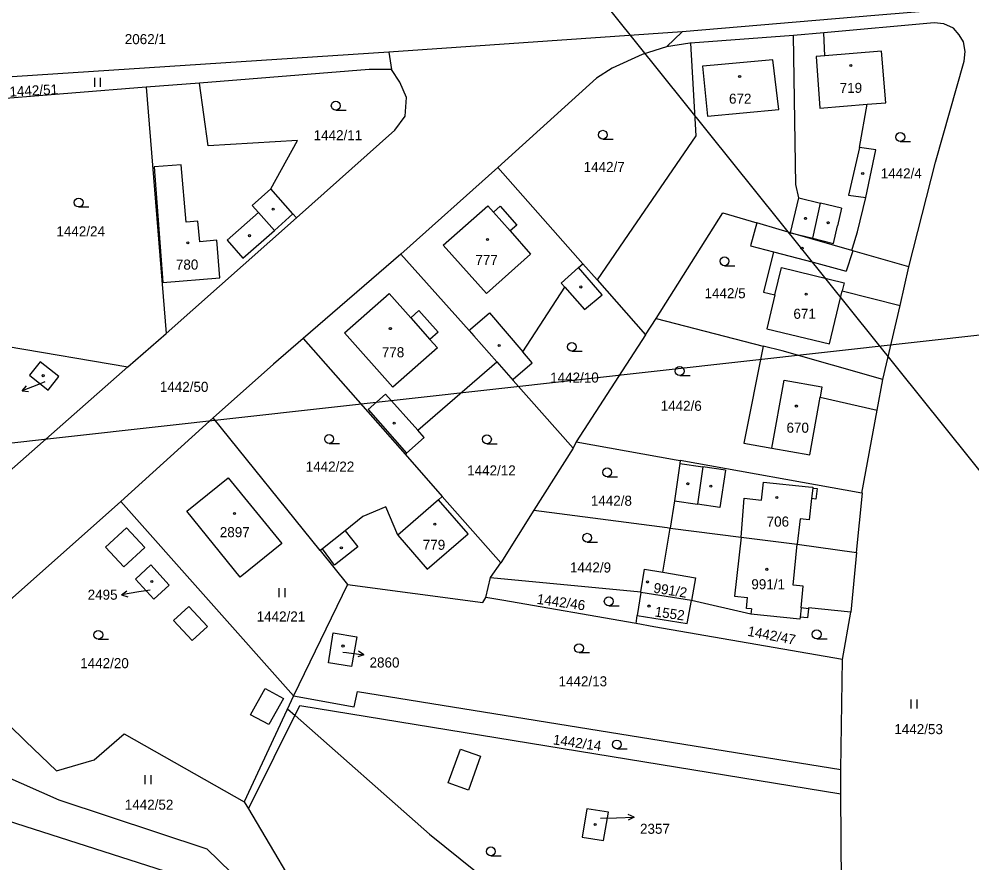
# Model space of a CAD drawing. Extents: x -794765 to -785424, y -1118958 to -1108731.
# Drawn here: x -792786.8 to -792625.5, y -1110305.2 to -1110162.4 of the extents above; entities that cross this region are included whole.
import ezdxf

# ---------------------------------------------------------------- set-up
doc = ezdxf.new("R2010")
doc.units = 0
for name, color, linetype in [('Level 66', 7, 'Continuous'), ('Level 71', 7, 'Continuous'), ('Level 75', 7, 'Continuous'), ('Level 76', 7, 'Continuous'), ('Level 77', 7, 'Continuous'), ('Level 79', 7, 'Continuous'), ('Level 80', 7, 'Continuous'), ('Level 81', 7, 'Continuous')]:
    doc.layers.add(name, color=color, linetype=linetype)

msp = doc.modelspace()

# ---------------------------------------------------------------- linework, layer by layer
at = {"layer": 'Level 66'}
for p, q in [((-792773.98, -1110173.85), (-792773.98, -1110172.35)), ((-792772.98, -1110173.85), (-792772.98, -1110172.35)), ((-792733.19, -1110177.79), (-792731.44, -1110177.79)), ((-792687.99, -1110182.71), (-792686.24, -1110182.71)), ((-792637.66, -1110183.1), (-792635.91, -1110183.1)), ((-792776.7, -1110194.19), (-792774.95, -1110194.19)), ((-792667.4, -1110204.13), (-792665.65, -1110204.13)), ((-792693.24, -1110218.62), (-792691.49, -1110218.62)), ((-792674.99, -1110222.72), (-792673.24, -1110222.72)), ((-792734.31, -1110234.22), (-792732.56, -1110234.22)), ((-792707.61, -1110234.27), (-792705.86, -1110234.27)), ((-792687.26, -1110239.87), (-792685.51, -1110239.87)), ((-792690.64, -1110250.94), (-792688.89, -1110250.94)), ((-792742.74, -1110260.23), (-792742.74, -1110258.73)), ((-792741.74, -1110260.23), (-792741.74, -1110258.73)), ((-792686.99, -1110261.71), (-792685.24, -1110261.71)), ((-792773.38, -1110267.38), (-792771.63, -1110267.38)), ((-792651.8, -1110267.29), (-792650.05, -1110267.29)), ((-792692.02, -1110269.64), (-792690.27, -1110269.64)), ((-792635.81, -1110279.08), (-792635.81, -1110277.58)), ((-792634.81, -1110279.08), (-792634.81, -1110277.58)), ((-792685.62, -1110285.93), (-792683.87, -1110285.93)), ((-792765.43, -1110291.89), (-792765.43, -1110290.39)), ((-792764.43, -1110291.89), (-792764.43, -1110290.39)), ((-792706.95, -1110304.04), (-792705.2, -1110304.04))]:
    msp.add_line(p, q, dxfattribs=at)
for centre in [(-792733.19, -1110177.04), (-792687.99, -1110181.96), (-792637.66, -1110182.35), (-792776.7, -1110193.44), (-792667.4, -1110203.38), (-792693.24, -1110217.87), (-792674.99, -1110221.97), (-792734.31, -1110233.47), (-792707.61, -1110233.52), (-792687.26, -1110239.12), (-792690.64, -1110250.19), (-792686.99, -1110260.96), (-792773.38, -1110266.63), (-792651.8, -1110266.54), (-792692.02, -1110268.89), (-792685.62, -1110285.18), (-792706.95, -1110303.29)]:
    msp.add_circle(centre, 0.75, dxfattribs=at)
at = {"layer": 'Level 71'}
for points in [[(-791938.08, -1109742.36), (-792598.01, -1110271.46), (-792786.15, -1110036.8), (-792126.22, -1109507.7)], [(-792522.06, -1110204.41), (-792422.02, -1111099.6), (-792720.93, -1111133), (-792820.96, -1110237.81)]]:
    msp.add_lwpolyline(points, close=True, dxfattribs=at)
at = {"layer": 'Level 75'}
for p, q in [((-792674.54, -1110164.53), (-792724.21, -1110167.98)), ((-792677.2, -1110167.06), (-792674.54, -1110164.53)), ((-792655.73, -1110165.18), (-792673.16, -1110166.45)), ((-792650.59, -1110164.71), (-792655.73, -1110165.18)), ((-792724.21, -1110167.98), (-792723.77, -1110170.89)), ((-792756.24, -1110173.2), (-792765.3, -1110173.93)), ((-792765.3, -1110173.93), (-792791.78, -1110176.05)), ((-792765.3, -1110173.93), (-792761.9, -1110215.62)), ((-792705.77, -1110187.49), (-792722.17, -1110202.16)), ((-792691.37, -1110203.81), (-792705.77, -1110187.49)), ((-792761.9, -1110215.62), (-792739.85, -1110196)), ((-792645.87, -1110201.53), (-792656.23, -1110198.55)), ((-792722.17, -1110202.16), (-792738.73, -1110216.47)), ((-792691.37, -1110203.81), (-792688.97, -1110206.53)), ((-792637.65, -1110210.85), (-792636.2, -1110204.31)), ((-792688.97, -1110206.53), (-792680.77, -1110215.83)), ((-792640.62, -1110223.39), (-792637.65, -1110210.85)), ((-792680.77, -1110215.83), (-792678.99, -1110213.07)), ((-792678.99, -1110213.07), (-792660.86, -1110217.73)), ((-792768.39, -1110221.23), (-792761.9, -1110215.62)), ((-792738.73, -1110216.47), (-792721.47, -1110236.05)), ((-792680.77, -1110215.83), (-792692.49, -1110233.97)), ((-792788.97, -1110217.76), (-792768.39, -1110221.23)), ((-792705.94, -1110220.41), (-792703.16, -1110223.56)), ((-792703.16, -1110223.56), (-792693.01, -1110235.03)), ((-792641.57, -1110228.57), (-792640.62, -1110223.39)), ((-792644.16, -1110242.64), (-792641.57, -1110228.57)), ((-792753.93, -1110229.88), (-792769.54, -1110244.05)), ((-792735.82, -1110252.35), (-792753.93, -1110229.88)), ((-792692.49, -1110233.97), (-792693.01, -1110235.03)), ((-792721.47, -1110236.05), (-792715.17, -1110243.19)), ((-792693.01, -1110235.03), (-792699.65, -1110245.51)), ((-792644.16, -1110242.64), (-792674.88, -1110237.13)), ((-792769.54, -1110244.05), (-792799.79, -1110270.88)), ((-792740.34, -1110276.96), (-792769.54, -1110244.05)), ((-792705.28, -1110254.41), (-792715.17, -1110243.19)), ((-792699.65, -1110245.51), (-792705.28, -1110254.41)), ((-792677.84, -1110256.04), (-792676.62, -1110248.54)), ((-792735.82, -1110252.35), (-792731.19, -1110258.09)), ((-792645.08, -1110252.7), (-792646.01, -1110262.76)), ((-792707, -1110256.94), (-792705.28, -1110254.41)), ((-792707.82, -1110260.28), (-792707, -1110256.94)), ((-792707, -1110256.94), (-792681.54, -1110259.37)), ((-792731.19, -1110258.09), (-792740.34, -1110276.96)), ((-792681.55, -1110259.43), (-792682.17, -1110263.35)), ((-792681.55, -1110259.43), (-792681.54, -1110259.37)), ((-792673.01, -1110260.82), (-792681.55, -1110259.43)), ((-792682.38, -1110264.72), (-792682.17, -1110263.35)), ((-792647.45, -1110270.81), (-792646.01, -1110262.76)), ((-792647.73, -1110289.44), (-792647.45, -1110270.81)), ((-792740.34, -1110276.96), (-792748.68, -1110294.88)), ((-792647.69, -1110293.54), (-792647.73, -1110289.44)), ((-792647.35, -1110350.05), (-792647.69, -1110293.54)), ((-792748.68, -1110294.88), (-792747.96, -1110296.1))]:
    msp.add_line(p, q, dxfattribs=at)
for points in [[(-792594.35, -1110157.78), (-792616.04, -1110159.6), (-792641.97, -1110161.78), (-792674.54, -1110164.53)], [(-792636.2, -1110204.31), (-792631.71, -1110186.61), (-792626.82, -1110169.51), (-792626.68, -1110167.87), (-792626.94, -1110166.21), (-792627.67, -1110165.03), (-792628.66, -1110163.9), (-792630.27, -1110163.16), (-792631.9, -1110162.99), (-792650.59, -1110164.71)], [(-792656.23, -1110198.55), (-792654.82, -1110192.66), (-792655.33, -1110190.39), (-792655.73, -1110165.18)], [(-792645.87, -1110201.53), (-792645.74, -1110201.14), (-792644.89, -1110198.38), (-792643.49, -1110192.57), (-792641.81, -1110184.53), (-792644.56, -1110184.12), (-792643.28, -1110176.8), (-792640.09, -1110176.54), (-792640.81, -1110167.82), (-792650.4, -1110168.59), (-792650.59, -1110164.71)], [(-792673.16, -1110166.45), (-792672.26, -1110182.14), (-792682.99, -1110197.8), (-792688.97, -1110206.53)], [(-792673.16, -1110166.45), (-792673.25, -1110166.46), (-792677.2, -1110167.06)], [(-792724.21, -1110167.98), (-792821.65, -1110174.35), (-792836.73, -1110180.03)], [(-792677.2, -1110167.06), (-792681.35, -1110168.35), (-792686.39, -1110170.67), (-792689.06, -1110172.4), (-792705.77, -1110187.49)], [(-792723.77, -1110170.89), (-792727.53, -1110170.89), (-792756.24, -1110173.2)], [(-792739.85, -1110196), (-792723.19, -1110181.17), (-792721.47, -1110178.8), (-792721.22, -1110175.68), (-792722.34, -1110173.08), (-792723.77, -1110170.89)], [(-792739.85, -1110196), (-792740.43, -1110195.35), (-792744.17, -1110191.11), (-792739.65, -1110182.91), (-792754.78, -1110183.81), (-792756.24, -1110173.2)], [(-792678.99, -1110213.07), (-792667.71, -1110195.2), (-792661.95, -1110196.88)], [(-792661.95, -1110196.88), (-792662.98, -1110200.74), (-792659.09, -1110201.77), (-792660.81, -1110208.6), (-792658.87, -1110209.07), (-792660.24, -1110214.79), (-792649.61, -1110217.33), (-792647.48, -1110208.4), (-792637.65, -1110210.85)], [(-792656.23, -1110198.55), (-792658.14, -1110197.99), (-792661.95, -1110196.88)], [(-792722.17, -1110202.16), (-792710.64, -1110215.1), (-792709.81, -1110216.03), (-792705.94, -1110220.41)], [(-792636.2, -1110204.31), (-792645.67, -1110201.59), (-792645.87, -1110201.53)], [(-792703.16, -1110223.56), (-792703.14, -1110223.32), (-792699.94, -1110220.59), (-792701.55, -1110218.71), (-792694.44, -1110207.78), (-792691.1, -1110211.55), (-792688.13, -1110209.06), (-792692.09, -1110204.45), (-792691.37, -1110203.81)], [(-792738.73, -1110216.47), (-792743.75, -1110220.82), (-792753.93, -1110229.88)], [(-792660.86, -1110217.73), (-792664.12, -1110234.17), (-792659.38, -1110235.02), (-792652.98, -1110236.17), (-792651.22, -1110226.38), (-792641.57, -1110228.57)], [(-792640.62, -1110223.39), (-792657.62, -1110218.56), (-792660.86, -1110217.73)], [(-792832.52, -1110277.99), (-792822.21, -1110268.85), (-792813.91, -1110261.49), (-792801.89, -1110250.87), (-792796.66, -1110246.15), (-792768.39, -1110221.23)], [(-792783.22, -1110220.39), (-792785.04, -1110222.69), (-792781.87, -1110225.18), (-792780.07, -1110222.89), (-792783.22, -1110220.39)], [(-792721.47, -1110236.05), (-792721.24, -1110235.85), (-792718.24, -1110233.2), (-792719.31, -1110231.99), (-792705.94, -1110220.41)], [(-792692.49, -1110233.97), (-792675.56, -1110237.01), (-792674.88, -1110237.13)], [(-792674.88, -1110237.13), (-792674.95, -1110237.64), (-792675.88, -1110243.96), (-792676.62, -1110248.54)], [(-792749.36, -1110256.86), (-792758.41, -1110245.67), (-792751.37, -1110240.02), (-792742.31, -1110251.18), (-792749.36, -1110256.86)], [(-792715.17, -1110243.19), (-792715.82, -1110243.76), (-792722.68, -1110249.74), (-792724.72, -1110244.95), (-792728.6, -1110246.6), (-792731.57, -1110248.99), (-792735.46, -1110252.06), (-792735.82, -1110252.35)], [(-792645.08, -1110252.7), (-792644.03, -1110242.66), (-792644.16, -1110242.64)], [(-792699.65, -1110245.51), (-792677.11, -1110248.48), (-792676.62, -1110248.54)], [(-792676.62, -1110248.54), (-792664.58, -1110250.11), (-792655.1, -1110251.26), (-792645.08, -1110252.7)], [(-792761.37, -1110258.2), (-792763.97, -1110260.6), (-792767.1, -1110257.22), (-792764.46, -1110254.78), (-792761.37, -1110258.2)], [(-792681.54, -1110259.37), (-792680.93, -1110255.52), (-792677.84, -1110256.04)], [(-792677.84, -1110256.04), (-792672.3, -1110256.96), (-792673.01, -1110260.82)], [(-792731.19, -1110258.09), (-792708.3, -1110261.17), (-792707.82, -1110260.28)], [(-792682.38, -1110264.72), (-792705.08, -1110260.76), (-792707.82, -1110260.28)], [(-792682.17, -1110263.35), (-792673.72, -1110264.68), (-792673.01, -1110260.82)], [(-792646.01, -1110262.76), (-792653.19, -1110262.08), (-792653.21, -1110262.2), (-792653.37, -1110263.75), (-792654.6, -1110263.62), (-792654.64, -1110263.97), (-792662.95, -1110263.1), (-792673.01, -1110260.82)], [(-792647.45, -1110270.81), (-792679.36, -1110265.25), (-792682.38, -1110264.72)], [(-792729.64, -1110266.97), (-792730.5, -1110271.99), (-792734.43, -1110271.34), (-792733.61, -1110266.29), (-792729.64, -1110266.97)], [(-792799.79, -1110270.88), (-792785.68, -1110284.61), (-792780.46, -1110289.67), (-792774.1, -1110287.81), (-792768.98, -1110283.36), (-792748.68, -1110294.88)], [(-792740.34, -1110276.96), (-792730.09, -1110278.81), (-792729.49, -1110276.2), (-792688.62, -1110282.82), (-792647.73, -1110289.44)], [(-792747.96, -1110296.1), (-792739.25, -1110278.59), (-792647.69, -1110293.54)], [(-792810.95, -1110280.9), (-792780.07, -1110294.56), (-792755.03, -1110302.83), (-792738.35, -1110319.04), (-792720.66, -1110333.41), (-792681.61, -1110364.96), (-792649.52, -1110392.89)], [(-792614.4, -1110416.41), (-792624.78, -1110416.77), (-792634.65, -1110411.27), (-792666.12, -1110385.5), (-792684.9, -1110369.28), (-792739.95, -1110324.15), (-792759.16, -1110307.61), (-792800.59, -1110294.35), (-792820.87, -1110289.8)], [(-792747.96, -1110296.1), (-792737.31, -1110314.17), (-792715.9, -1110332.58), (-792713.52, -1110333.73), (-792705.15, -1110333.15), (-792703.51, -1110325.45), (-792682.4, -1110332.77), (-792649.82, -1110351.57), (-792647.35, -1110350.05)], [(-792687.05, -1110296.66), (-792690.69, -1110296.06), (-792691.48, -1110300.88), (-792687.88, -1110301.46), (-792687.05, -1110296.66)]]:
    msp.add_lwpolyline(points, dxfattribs=at)
at = {"layer": 'Level 77'}
for p, q in [((-792659.22, -1110169.28), (-792669.18, -1110170.19)), ((-792658.21, -1110177.7), (-792659.22, -1110169.28)), ((-792650.4, -1110168.59), (-792651.9, -1110168.72)), ((-792651.9, -1110168.72), (-792651.25, -1110177.45)), ((-792669.18, -1110170.19), (-792671.15, -1110170.37)), ((-792671.15, -1110170.37), (-792670.26, -1110178.84)), ((-792670.26, -1110178.84), (-792658.21, -1110177.7)), ((-792651.25, -1110177.45), (-792643.28, -1110176.8)), ((-792644.56, -1110184.12), (-792646.42, -1110192.17)), ((-792759.37, -1110187.03), (-792763.92, -1110187.38)), ((-792763.92, -1110187.38), (-792762.43, -1110206.98)), ((-792758.49, -1110196.74), (-792759.37, -1110187.03)), ((-792744.17, -1110191.11), (-792747.35, -1110193.91)), ((-792646.42, -1110192.17), (-792643.49, -1110192.57)), ((-792747.35, -1110193.91), (-792746.28, -1110195.11)), ((-792715, -1110200.64), (-792707.43, -1110193.98)), ((-792707.43, -1110193.98), (-792706.49, -1110195.05)), ((-792706.49, -1110195.05), (-792705.36, -1110194.06)), ((-792705.36, -1110194.06), (-792702.55, -1110197.24)), ((-792654.82, -1110192.66), (-792651.15, -1110193.54)), ((-792652.44, -1110199.49), (-792651.15, -1110193.54)), ((-792647.63, -1110194.38), (-792651.15, -1110193.54)), ((-792746.28, -1110195.11), (-792751.56, -1110199.82)), ((-792746.28, -1110195.11), (-792743.58, -1110198.15)), ((-792740.43, -1110195.35), (-792743.58, -1110198.15)), ((-792706.49, -1110195.05), (-792703.67, -1110198.23)), ((-792647.63, -1110194.38), (-792648.3, -1110197.4)), ((-792756.52, -1110196.57), (-792758.49, -1110196.74)), ((-792756.17, -1110200.07), (-792756.52, -1110196.57)), ((-792702.55, -1110197.24), (-792703.67, -1110198.23)), ((-792648.96, -1110200.35), (-792648.3, -1110197.4)), ((-792748.91, -1110202.88), (-792743.58, -1110198.15)), ((-792703.67, -1110198.23), (-792700.21, -1110202.16)), ((-792656.23, -1110198.55), (-792652.44, -1110199.49)), ((-792753.33, -1110199.81), (-792756.17, -1110200.07)), ((-792752.83, -1110206.18), (-792753.33, -1110199.81)), ((-792751.56, -1110199.82), (-792748.91, -1110202.88)), ((-792707.69, -1110208.84), (-792715, -1110200.64)), ((-792652.44, -1110199.49), (-792648.96, -1110200.35)), ((-792700.21, -1110202.16), (-792707.69, -1110208.84)), ((-792659.09, -1110201.77), (-792652.4, -1110203.53)), ((-792652.4, -1110203.53), (-792646.81, -1110205.04)), ((-792692.09, -1110204.45), (-792695.07, -1110207.07)), ((-792658.87, -1110209.07), (-792657.77, -1110204.46)), ((-792657.77, -1110204.46), (-792647.15, -1110207.02)), ((-792762.43, -1110206.98), (-792752.83, -1110206.18)), ((-792695.07, -1110207.07), (-792694.44, -1110207.78)), ((-792647.15, -1110207.02), (-792647.48, -1110208.4)), ((-792731.7, -1110215.49), (-792724.14, -1110208.83)), ((-792724.14, -1110208.83), (-792720.5, -1110212.95)), ((-792720.5, -1110212.95), (-792719.13, -1110211.73)), ((-792719.13, -1110211.73), (-792715.88, -1110215.4)), ((-792720.5, -1110212.95), (-792717.26, -1110216.62)), ((-792710.4, -1110214.9), (-792707.17, -1110212.13)), ((-792707.17, -1110212.13), (-792701.55, -1110218.71)), ((-792710.4, -1110214.9), (-792710.64, -1110215.1)), ((-792723.52, -1110224.72), (-792731.7, -1110215.49)), ((-792715.88, -1110215.4), (-792717.26, -1110216.62)), ((-792717.26, -1110216.62), (-792715.99, -1110218.05)), ((-792715.99, -1110218.05), (-792723.52, -1110224.72)), ((-792659.38, -1110235.02), (-792657.31, -1110223.5)), ((-792657.31, -1110223.5), (-792650.91, -1110224.65)), ((-792650.91, -1110224.65), (-792651.22, -1110226.38)), ((-792727.73, -1110228.5), (-792724.75, -1110225.87)), ((-792724.75, -1110225.87), (-792719.31, -1110231.99)), ((-792727.73, -1110228.5), (-792721.24, -1110235.85)), ((-792674.95, -1110237.64), (-792671.05, -1110238.21)), ((-792671.05, -1110238.21), (-792672, -1110244.53)), ((-792667.25, -1110238.77), (-792671.05, -1110238.21)), ((-792667.25, -1110238.77), (-792668.18, -1110245.09)), ((-792661.14, -1110243.81), (-792660.83, -1110240.76)), ((-792660.83, -1110240.76), (-792653.17, -1110241.54)), ((-792653.17, -1110241.54), (-792652.43, -1110241.61)), ((-792652.45, -1110241.79), (-792652.66, -1110243.57)), ((-792652.43, -1110241.61), (-792652.45, -1110241.79)), ((-792652.45, -1110241.79), (-792651.75, -1110241.87)), ((-792651.75, -1110241.87), (-792651.96, -1110243.65)), ((-792710.81, -1110249.52), (-792715.82, -1110243.76)), ((-792675.88, -1110243.96), (-792672, -1110244.53)), ((-792664.58, -1110250.11), (-792664.1, -1110243.51)), ((-792664.1, -1110243.51), (-792661.14, -1110243.81)), ((-792652.66, -1110243.57), (-792653.07, -1110247.14)), ((-792651.96, -1110243.65), (-792652.66, -1110243.57)), ((-792668.18, -1110245.09), (-792672, -1110244.53)), ((-792654.62, -1110246.98), (-792655.1, -1110251.26)), ((-792653.07, -1110247.14), (-792654.62, -1110246.98)), ((-792772.13, -1110251.78), (-792768.58, -1110248.49)), ((-792768.58, -1110248.49), (-792765.5, -1110251.82)), ((-792731.57, -1110248.99), (-792729.43, -1110251.71)), ((-792722.68, -1110249.74), (-792717.72, -1110255.53)), ((-792717.72, -1110255.53), (-792710.81, -1110249.52)), ((-792664.58, -1110250.11), (-792665.71, -1110260.09)), ((-792769.05, -1110255.11), (-792772.13, -1110251.78)), ((-792765.5, -1110251.82), (-792769.05, -1110255.11)), ((-792733.38, -1110254.82), (-792735.46, -1110252.06)), ((-792729.43, -1110251.71), (-792733.38, -1110254.82)), ((-792655.77, -1110258.22), (-792655.1, -1110251.26)), ((-792654.07, -1110258.39), (-792655.77, -1110258.22)), ((-792654.45, -1110262.08), (-792654.07, -1110258.39)), ((-792665.71, -1110260.09), (-792663.51, -1110260.31)), ((-792663.7, -1110262.19), (-792663.51, -1110260.31)), ((-792760.62, -1110264.22), (-792758.03, -1110261.82)), ((-792758.03, -1110261.82), (-792754.91, -1110265.2)), ((-792662.86, -1110262.24), (-792663.7, -1110262.19)), ((-792662.86, -1110262.24), (-792662.95, -1110263.1)), ((-792654.45, -1110262.08), (-792654.6, -1110263.62)), ((-792653.21, -1110262.2), (-792654.45, -1110262.08)), ((-792757.5, -1110267.59), (-792760.62, -1110264.22)), ((-792754.91, -1110265.2), (-792757.5, -1110267.59)), ((-792747.59, -1110280.16), (-792745.16, -1110275.69)), ((-792745.16, -1110275.69), (-792742.01, -1110277.41)), ((-792742.01, -1110277.41), (-792744.54, -1110281.83)), ((-792744.54, -1110281.83), (-792747.59, -1110280.16)), ((-792714.15, -1110291.69), (-792712.1, -1110285.96)), ((-792712.1, -1110285.96), (-792708.7, -1110287.19)), ((-792708.7, -1110287.19), (-792710.75, -1110292.91)), ((-792710.75, -1110292.91), (-792714.15, -1110291.69))]:
    msp.add_line(p, q, dxfattribs=at)
msp.add_lwpolyline([(-792645.67, -1110201.59), (-792645.73, -1110201.76), (-792646.81, -1110205.04)], dxfattribs=at)
at = {"layer": 'Level 79'}
for centre in [(-792646.04, -1110170.25), (-792664.84, -1110172.09), (-792644.02, -1110188.52), (-792743.77, -1110194.57), (-792653.7, -1110196.12), (-792649.85, -1110196.85), (-792747.8, -1110199.04), (-792758.23, -1110200.27), (-792707.52, -1110199.7), (-792654.29, -1110201.18), (-792691.7, -1110207.73), (-792653.59, -1110208.95), (-792723.95, -1110214.78), (-792705.55, -1110217.64), (-792782.72, -1110222.75), (-792655.24, -1110227.89), (-792723.29, -1110230.79), (-792673.62, -1110241.04), (-792669.7, -1110241.45), (-792658.56, -1110243.36), (-792750.31, -1110246.07), (-792716.42, -1110247.9), (-792732.24, -1110251.88), (-792660.25, -1110255.54), (-792764.31, -1110257.59), (-792680.43, -1110257.67), (-792680.18, -1110261.75), (-792731.96, -1110268.52), (-792689.28, -1110298.72)]:
    msp.add_circle(centre, 0.175, dxfattribs=at)
at = {"layer": 'Level 80'}
for p, q in [((-792783.47, -1110224.22), (-792786.27, -1110225.29)), ((-792786.27, -1110225.29), (-792785.52, -1110224.47)), ((-792782.4, -1110223.81), (-792783.47, -1110224.22)), ((-792786.27, -1110225.29), (-792785.16, -1110225.4)), ((-792769.45, -1110259.83), (-792768.54, -1110259.18)), ((-792766.49, -1110259.36), (-792769.45, -1110259.83)), ((-792769.45, -1110259.83), (-792768.39, -1110260.17)), ((-792764.57, -1110259.06), (-792766.49, -1110259.36)), ((-792731.98, -1110269.55), (-792731.39, -1110269.62)), ((-792731.39, -1110269.62), (-792728.41, -1110269.99)), ((-792728.41, -1110269.99), (-792729.47, -1110270.36)), ((-792728.41, -1110269.99), (-792729.34, -1110269.37)), ((-792682.7, -1110297.49), (-792683.72, -1110297.02)), ((-792688.37, -1110297.69), (-792685.7, -1110297.59)), ((-792685.7, -1110297.59), (-792682.7, -1110297.49)), ((-792682.7, -1110297.49), (-792683.68, -1110298.02))]:
    msp.add_line(p, q, dxfattribs=at)
at = {"layer": 'Level 81'}
msp.add_lwpolyline([(-792741.35, -1110279.13), (-792740.08, -1110280.26), (-792717.32, -1110300.4), (-792684.15, -1110327.06), (-792667.44, -1110341.4), (-792655.62, -1110351.55), (-792646.39, -1110359.72), (-792637.05, -1110367.99), (-792618.28, -1110384.61), (-792617.02, -1110385.47)], dxfattribs=at)

# ---------------------------------------------------------------- texts
at = {"layer": 'Level 76'}
for s, p in [('2062/1', (-792768.89, -1110166.62)), ('719', (-792647.91, -1110174.87)), ('672', (-792666.64, -1110176.7)), ('1442/11', (-792736.93, -1110182.89)), ('1442/7', (-792691.24, -1110188.26)), ('1442/4', (-792640.97, -1110189.35)), ('1442/24', (-792780.46, -1110199.16)), ('777', (-792709.56, -1110204)), ('780', (-792760.24, -1110204.79)), ('1442/5', (-792670.78, -1110209.64)), ('671', (-792655.74, -1110213.12)), ('778', (-792725.39, -1110219.63)), ('1442/10', (-792696.9, -1110223.92)), ('1442/50', (-792762.96, -1110225.49)), ('1442/6', (-792678.2, -1110228.7)), ('670', (-792656.91, -1110232.41)), ('1442/22', (-792738.27, -1110238.99)), ('1442/12', (-792710.95, -1110239.64)), ('1442/8', (-792690.02, -1110244.77)), ('706', (-792660.27, -1110248.3)), ('2897', (-792752.81, -1110250.09)), ('779', (-792718.46, -1110252.23)), ('1442/9', (-792693.55, -1110256.07)), ('991/1', (-792662.86, -1110258.91)), ('2495', (-792775.17, -1110260.68)), ('1442/21', (-792746.57, -1110264.37)), ('1442/20', (-792776.43, -1110272.27)), ('2860', (-792727.47, -1110272.16)), ('1442/13', (-792695.49, -1110275.34)), ('1442/53', (-792638.66, -1110283.44)), ('1442/52', (-792768.89, -1110296.23)), ('2357', (-792681.7, -1110300.31))]:
    msp.add_text(s, height=1.7, dxfattribs=at).set_placement(p)
for s, rotation, p in [('1442/51', 3, (-792788.36, -1110175.52)), ('991/2', 351, (-792679.51, -1110259.47)), ('1442/46', 352, (-792699.24, -1110261.36)), ('1552', 352, (-792679.29, -1110263.51)), ('1442/47', 349, (-792663.61, -1110266.77)), ('1442/14', 352, (-792696.51, -1110285.16))]:
    msp.add_text(s, height=1.7, rotation=rotation, dxfattribs=at).set_placement(p)

doc.saveas('drawing.dxf')
